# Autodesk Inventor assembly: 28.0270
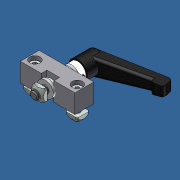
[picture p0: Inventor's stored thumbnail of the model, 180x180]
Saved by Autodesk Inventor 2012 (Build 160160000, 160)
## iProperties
Created: 2007-06
Part Number: 28.0270
Document SubType Name: Assembly
Designer: Andy Moles
Mass: 228.624 g
Surface Area: 187.848 cm^2
Volume: 42.6908 cm^3
Density: 5.35534 g/cm^3
Description: SLIDE CLAMPING UNIT
Vendor: A
Author: Andy Moles
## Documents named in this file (8)
- C:\Andys Backup Data\ANDY'S INVENTOR\INVENTOR LIBRARIES\PARTS LIBRARY\COMPONENTS LR\SUBCOMPONENTS\28.0270 SLIDE CLAMPING UNIT 2mm OFFSET.iam
- C:\Andys Backup Data\ANDY'S INVENTOR\INVENTOR LIBRARIES\PARTS LIBRARY\COMPONENTS LR\SUBCOMPONENTS\28.0270 SLIDE CLAMPING UNIT AL BLOCK.ipt
- C:\Andys Backup Data\ANDY'S INVENTOR\INVENTOR LIBRARIES\PARTS LIBRARY\FASTENING ELEMENTS\SCREWS CAP\21.1242 M6X25.ipt
- C:\Andys Backup Data\ANDY'S INVENTOR\INVENTOR LIBRARIES\PARTS LIBRARY\FASTENING ELEMENTS\NUTS\21.1330 M6 SQUARE NUT.ipt
- C:\Andys Backup Data\ANDY'S INVENTOR\INVENTOR LIBRARIES\PARTS LIBRARY\FASTENING ELEMENTS\WASHERS\WASHER M8 PLASTIC 17mm OD.ipt
- C:\Andys Backup Data\ANDY'S INVENTOR\INVENTOR LIBRARIES\PARTS LIBRARY\COMPONENTS LR\SUBCOMPONENTS\28.0270 SLIDE CLAMPING UNIT HANDLE.ipt
- C:\Andys Backup Data\ANDY'S INVENTOR\INVENTOR LIBRARIES\PARTS LIBRARY\COMPONENTS LR\SUBCOMPONENTS\28.0270 THREADED STUD.ipt
- C:\Andys Backup Data\ANDY'S INVENTOR\INVENTOR LIBRARIES\PARTS LIBRARY\FASTENING ELEMENTS\NUTS\21.1351 M8 SQUARE NUT.ipt
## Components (12 placed, 7 different names)
1. 28.0270 SLIDE CLAMPING UNIT AL BLOCK:1 — Insert:1, Insert:2, Insert:3, Insert:4, Insert:5, Insert:7
2. 21.1242 M6 x 25:1 — Insert:1
3. 21.1242 M6 x 25:2 — Insert:2
4. 21.1330 M6 SQUARE NUT:1 — Insert:4
5. 21.1330 M6 SQUARE NUT:2 — Insert:3
6. WASHER M8 PLASTIC 17mm OD:1 — Insert:5, Insert:6
7. WASHER M8 PLASTIC 17mm OD:2 — Insert:6, Insert:8
8. WASHER M8 PLASTIC 17mm OD:3 — Insert:9, Mate:2, Insert:10
9. 28.0270 SLIDE CLAMPING UNIT HANDLE:1 — Insert:8
10. 28.0270 THREADED STUD:1 — Insert:7, Mate:1
11. 21.1351 M8 SQUARE NUT:1 — Mate:1, Insert:9
12. 21.1351 M8 SQUARE NUT:2 — Insert:10
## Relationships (12: Insert 10, Mate 2)
- Insert:1: 28.0270 SLIDE CLAMPING UNIT AL BLOCK:1 ↔ 21.1242 M6 x 25:1
- Insert:2: 28.0270 SLIDE CLAMPING UNIT AL BLOCK:1 ↔ 21.1242 M6 x 25:2
- Insert:3: 28.0270 SLIDE CLAMPING UNIT AL BLOCK:1 ↔ 21.1330 M6 SQUARE NUT:2
- Insert:4: 28.0270 SLIDE CLAMPING UNIT AL BLOCK:1 ↔ 21.1330 M6 SQUARE NUT:1
- Insert:5: 28.0270 SLIDE CLAMPING UNIT AL BLOCK:1 ↔ WASHER M8 PLASTIC 17mm OD:1
- Insert:6: WASHER M8 PLASTIC 17mm OD:1 ↔ WASHER M8 PLASTIC 17mm OD:2
- Insert:7: 28.0270 SLIDE CLAMPING UNIT AL BLOCK:1 ↔ 28.0270 THREADED STUD:1
- Insert:8: WASHER M8 PLASTIC 17mm OD:2 ↔ 28.0270 SLIDE CLAMPING UNIT HANDLE:1
- Mate:1: 28.0270 THREADED STUD:1 ↔ 21.1351 M8 SQUARE NUT:1
- Insert:9: WASHER M8 PLASTIC 17mm OD:3 ↔ 21.1351 M8 SQUARE NUT:1
- Mate:2: WASHER M8 PLASTIC 17mm OD:3
- Insert:10: WASHER M8 PLASTIC 17mm OD:3 ↔ 21.1351 M8 SQUARE NUT:2
